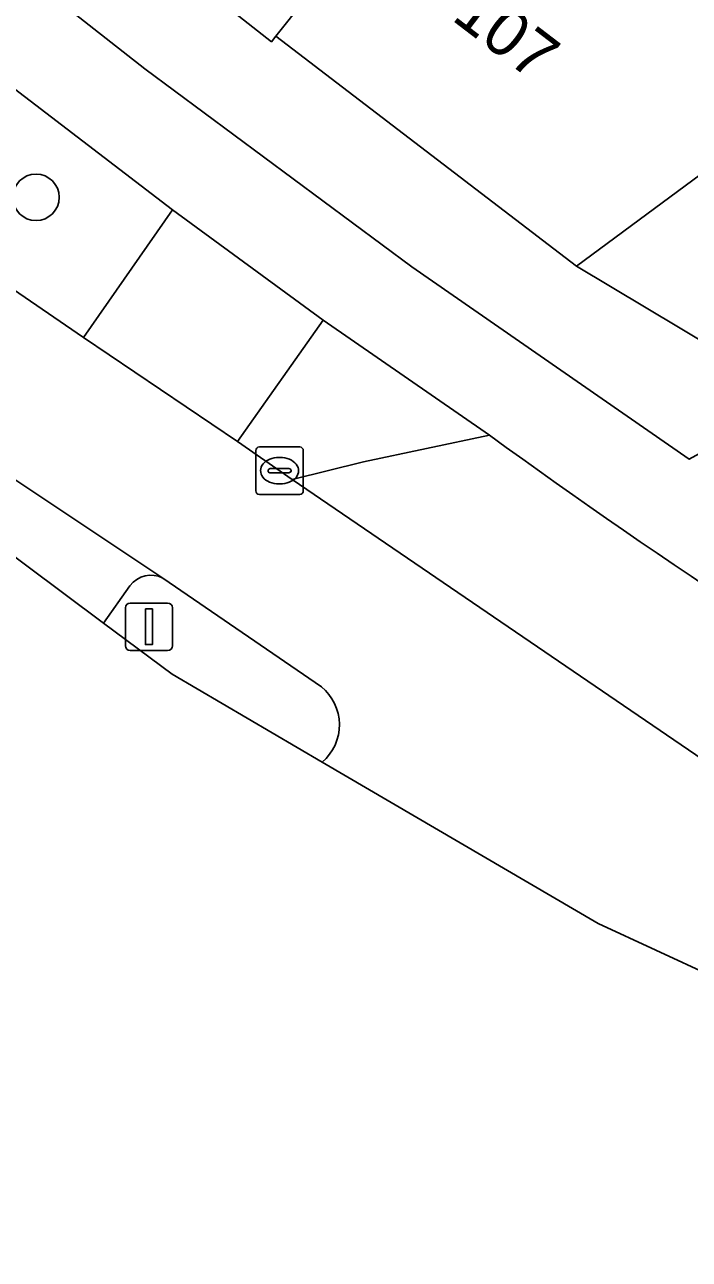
# Model space of a CAD drawing. Extents: x 161881 to 162523, y 381678 to 382381.
# Drawn here: x 162151.2 to 162165.21, y 381835.76 to 381861.78 of the extents above; entities that cross this region are included whole.
import ezdxf

# ---------------------------------------------------------------- set-up
doc = ezdxf.new("R2010")
doc.units = 0
for name, color, linetype in [('IMGEO_Berm_groen', 7, 'Continuous'), ('IMGEO_Boom', 7, 'Continuous'), ('IMGEO_Fietspad_open', 7, 'Continuous'), ('IMGEO_Kolk', 7, 'Continuous'), ('IMGEO_Lichtmast', 7, 'Continuous'), ('IMGEO_Pand', 7, 'Continuous'), ('IMGEO_Pand_nummerreeks', 7, 'Continuous'), ('IMGEO_Rijbaan_lokaal_gesloten', 7, 'Continuous'), ('IMGEO_Rijbaan_lokaal_open', 7, 'Continuous'), ('IMGEO_Verkeerseiland_open', 7, 'Continuous'), ('IMGEO_Voetpad_open', 7, 'Continuous')]:
    doc.layers.add(name, color=color, linetype=linetype)

msp = doc.modelspace()

# ---------------------------------------------------------------- linework, layer by layer
at = {"layer": 'IMGEO_Berm_groen'}
msp.add_lwpolyline([(162146.409, 381859.345), (162146.893, 381858.988), (162152.445, 381855.182), (162154.317, 381857.877), (162149.424, 381861.621)], dxfattribs=at)
msp.add_lwpolyline([(162157.492, 381855.554), (162155.688, 381852.991), (162156.84, 381852.193), (162158.34, 381852.564), (162160.998, 381853.125)], close=True, dxfattribs=at)
at = {"layer": 'IMGEO_Boom'}
msp.add_circle((162151.442, 381858.139), 0.489, dxfattribs=at)
at = {"layer": 'IMGEO_Fietspad_open'}
for points in [[(162165.207, 381852.621), (162159.359, 381856.676), (162153.733, 381860.844), (162148.22, 381865.171), (162143.628, 381869.029), (162139.164, 381873.055), (162135.64, 381876.643), (162133.655, 381878.876), (162129.811, 381883.512), (162122.303, 381893.442)], [(162120.359, 381890.101), (162124.284, 381884.836), (162127.27, 381881.044), (162130.724, 381876.875), (162133.224, 381874.067), (162136.556, 381870.68), (162137.791, 381869.113), (162137.664, 381869.027), (162143.785, 381866.108), (162144.072, 381865.971), (162149.424, 381861.621), (162154.317, 381857.877), (162157.492, 381855.554), (162160.998, 381853.125)]]:
    msp.add_lwpolyline(points, dxfattribs=at)
msp.add_arc((162242.708, 381965.423), 138.879, 233.95977, 239.66292, dxfattribs=at)
at = {"layer": 'IMGEO_Kolk'}
for p, q in [((162156.073, 381851.953), (162156.073, 381852.805)), ((162156.148, 381852.879), (162157, 381852.879)), ((162157.074, 381852.805), (162157.074, 381851.953)), ((162156.561, 381852.659), (162156.586, 381852.659)), ((162156.332, 381852.373), (162156.332, 381852.385)), ((162156.77, 381852.336), (162156.372, 381852.336)), ((162156.375, 381852.422), (162156.773, 381852.422)), ((162156.816, 381852.385), (162156.816, 381852.373)), ((162156.584, 381852.099), (162156.559, 381852.099)), ((162157, 381851.879), (162156.148, 381851.879))]:
    msp.add_line(p, q, dxfattribs=at)
for points in [[(162156.073, 381851.953), (162156.073, 381852.805)], [(162156.148, 381852.879), (162157, 381852.879)], [(162157.074, 381852.805), (162157.074, 381851.953)], [(162157, 381851.879), (162156.148, 381851.879)]]:
    msp.add_lwpolyline(points, dxfattribs=at)
for centre, radius, start, end in [((162156.15, 381852.803), 0.0765, 91.552, 178.448), ((162156.15, 381852.803), 0.0765, 91.552, 178.448), ((162156.998, 381852.803), 0.0765, 1.552, 88.448), ((162156.998, 381852.803), 0.0765, 1.552, 88.448), ((162156.372, 381852.382), 0.0403, 85.8775, 175.7526), ((162156.369, 381852.372), 0.0366, 178.938, 274.7102), ((162156.773, 381852.379), 0.043, 264.8664, 352.4533), ((162156.777, 381852.384), 0.0386, 1.7309, 96.639), ((162156.15, 381851.955), 0.0765, 181.552, 268.448), ((162156.15, 381851.955), 0.0765, 181.552, 268.448), ((162156.998, 381851.955), 0.0765, 271.552, 358.448), ((162156.998, 381851.955), 0.0765, 271.552, 358.448)]:
    msp.add_arc(centre, radius, start, end, dxfattribs=at)
for centre, major_axis, ratio, start_param, end_param in [((162156.56, 381852.379), (-0.387, 0.002), 0.722429, 4.712389, 7.853982), ((162156.585, 381852.379), (-0.39, 0.002), 0.717154, 1.570796, 4.712389)]:
    msp.add_ellipse(centre, major_axis=major_axis, ratio=ratio, start_param=start_param, end_param=end_param, dxfattribs=at)
at = {"layer": 'IMGEO_Lichtmast'}
for p, q in [((162153.426, 381849.591), (162154.216, 381849.591)), ((162154.216, 381849.591), (162153.426, 381849.591)), ((162153.326, 381848.691), (162153.326, 381849.491)), ((162153.326, 381849.491), (162153.326, 381848.691)), ((162154.316, 381849.491), (162154.316, 381848.691)), ((162154.316, 381848.691), (162154.316, 381849.491)), ((162154.216, 381848.591), (162153.426, 381848.591)), ((162153.426, 381848.591), (162154.216, 381848.591))]:
    msp.add_line(p, q, dxfattribs=at)
msp.add_lwpolyline([(162153.746, 381849.466), (162153.896, 381849.466), (162153.896, 381848.716), (162153.746, 381848.716), (162153.746, 381849.466)], dxfattribs=at)
for centre, start, end in [((162153.426, 381849.491), 90, 180), ((162153.426, 381849.491), 90, 180), ((162154.216, 381849.491), 0, 90), ((162154.216, 381849.491), 360, 90), ((162153.426, 381848.691), 180, 270), ((162153.426, 381848.691), 180, 270), ((162154.216, 381848.691), 270, 0), ((162154.216, 381848.691), 270, 0)]:
    msp.add_arc(centre, 0.1, start, end, dxfattribs=at)
at = {"layer": 'IMGEO_Pand'}
for points in [[(162167.706, 381866.247), (162166.625, 381867.135), (162166.397, 381869.331), (162167.982, 381870.977), (162172.99, 381864.214), (162173.176, 381864.352), (162176.595, 381866.681), (162173.642, 381870.716), (162171.2, 381874.055), (162168.933, 381877.15), (162167.482, 381875.329), (162166.814, 381874.49), (162162.639, 381869.248), (162160.713, 381866.829), (162156.495, 381861.533), (162162.832, 381856.692), (162170.693, 381862.513), (162168.29, 381864.451), (162167.194, 381865.56)], [(162162.639, 381869.248), (162160.651, 381870.809), (162162.185, 381872.764), (162160.06, 381874.431), (162152.281, 381864.662), (162156.403, 381861.418), (162156.495, 381861.533), (162160.713, 381866.829)]]:
    msp.add_lwpolyline(points, close=True, dxfattribs=at)
at = {"layer": 'IMGEO_Rijbaan_lokaal_gesloten'}
for points in [[(162157.474, 381846.239), (162163.289, 381842.84), (162270.956, 381793.049), (162271.685, 381794.828), (162265.892, 381797.201), (162264.88, 381797.509), (162260.412, 381799.413), (162255.206, 381801.667), (162254.636, 381801.98), (162216.47, 381819.118), (162200.955, 381826.085), (162199.963, 381826.58), (162197.222, 381827.799), (162186.613, 381832.56), (162184.638, 381833.581), (162180.636, 381835.815), (162176.308, 381838.737), (162175.355, 381839.579), (162172.48, 381841.526), (162156.84, 381852.193), (162155.688, 381852.991), (162152.445, 381855.182), (162146.893, 381858.988)], [(162146.637, 381855.183), (162149.998, 381852.855), (162154.116, 381850.115), (162157.455, 381847.822)]]:
    msp.add_lwpolyline(points, dxfattribs=at)
msp.add_arc((162156.804, 381847.023), 1.031, 310.5191, 50.8562, dxfattribs=at)
at = {"layer": 'IMGEO_Rijbaan_lokaal_open'}
for points in [[(162171.296, 381850.551), (162171.631, 381851.44), (162167.236, 381854.058), (162166.981, 381853.768), (162166.522, 381853.342), (162165.207, 381852.621)], [(162160.998, 381853.125), (162158.34, 381852.564), (162156.84, 381852.193), (162172.48, 381841.526), (162172.524, 381842.897), (162172.562, 381845.561)]]:
    msp.add_lwpolyline(points, dxfattribs=at)
msp.add_arc((162242.708, 381965.423), 138.879, 233.95977, 239.66292, dxfattribs=at)
at = {"layer": 'IMGEO_Verkeerseiland_open'}
for points in [[(162157.455, 381847.822), (162154.116, 381850.115)], [(162153.422, 381849.955), (162152.862, 381849.169), (162152.862, 381849.169), (162154.309, 381848.089), (162157.474, 381846.239)]]:
    msp.add_lwpolyline(points, dxfattribs=at)
for centre, radius, start, end in [((162153.862, 381849.633), 0.545, 62.18, 143.7851), ((162156.804, 381847.023), 1.031, 310.5191, 50.8562)]:
    msp.add_arc(centre, radius, start, end, dxfattribs=at)
at = {"layer": 'IMGEO_Voetpad_open'}
for points in [[(162222.611, 381898.266), (162222.089, 381899.341), (162219.928, 381897.942), (162200.679, 381884.262), (162189.26, 381875.839), (162187.895, 381874.832), (162187.997, 381874.692), (162184.9, 381872.437), (162184.296, 381873.278), (162182.635, 381872.084), (162180.973, 381870.888), (162181.45, 381870.226), (162178.278, 381867.945), (162176.595, 381866.681), (162173.176, 381864.352), (162172.99, 381864.214), (162170.693, 381862.513), (162162.832, 381856.692), (162167.236, 381854.058), (162167.602, 381854.382), (162169.555, 381856.117)], [(162148.22, 381865.171), (162153.733, 381860.844), (162159.359, 381856.676), (162165.207, 381852.621), (162166.522, 381853.342), (162166.981, 381853.768), (162167.236, 381854.058), (162162.832, 381856.692), (162156.495, 381861.533), (162156.403, 381861.418), (162152.281, 381864.662), (162148.108, 381867.983)], [(162154.116, 381850.115), (162149.998, 381852.855)], [(162149.598, 381851.604), (162152.862, 381849.169), (162152.862, 381849.169), (162153.422, 381849.955)]]:
    msp.add_lwpolyline(points, dxfattribs=at)
msp.add_lwpolyline([(162155.688, 381852.991), (162157.492, 381855.554), (162154.317, 381857.877), (162152.445, 381855.182)], close=True, dxfattribs=at)
msp.add_arc((162153.862, 381849.633), 0.545, 62.18, 143.7851, dxfattribs=at)

# ---------------------------------------------------------------- texts
at = {"layer": 'IMGEO_Pand_nummerreeks'}
msp.add_text('107', height=1, rotation=322.6202, dxfattribs=at).set_placement((162160.174, 381861.894))

doc.saveas('drawing.dxf')
